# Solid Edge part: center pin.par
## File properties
Author: Binay
Template: sync ansi part.par
Last saved by: TIET
Revision: 7
Application: Solid Edge
Accuracy: 0.990
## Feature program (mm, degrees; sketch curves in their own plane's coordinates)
sketch for "unnamed Hole 1" plane through (42.6694, 3.8175, 49.1782) normal (0, 0, 1) x-axis (1, 0, 0)
  hole centre (0.7149, -3.8175) bore radius 8.001
hole "unnamed Hole 1" through
pattern "unnamed Pattern 1" of "unnamed Hole 1"
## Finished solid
Body 1: solid body, 7 faces, 7 edges, 0 vertices.
  Faces by surface: cylinder 3, plane 3, cone 1
  Edges by curve: circle 7
Bounding box of the edges (mm): 34.290 x 34.290 x 76.200, from (26.2393, -17.145, -27.0218) to (60.5293, 17.145, 49.1782).
Cylindrical faces by radius (mm): R8.001 x1, R12.7 x1, R17.145 x1
Conical faces (half-angle, radius in mm at the cone's reference point): 45 deg R11.176 x1
Planar faces by outward normal: +z 1, -z 2
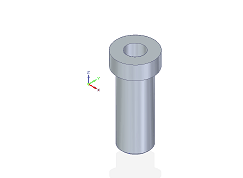
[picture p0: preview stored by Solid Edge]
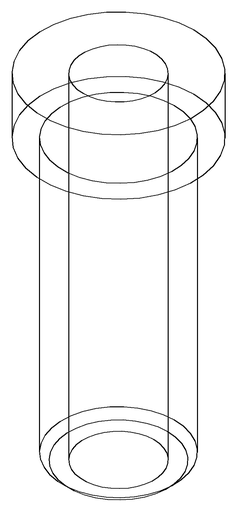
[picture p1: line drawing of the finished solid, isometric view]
